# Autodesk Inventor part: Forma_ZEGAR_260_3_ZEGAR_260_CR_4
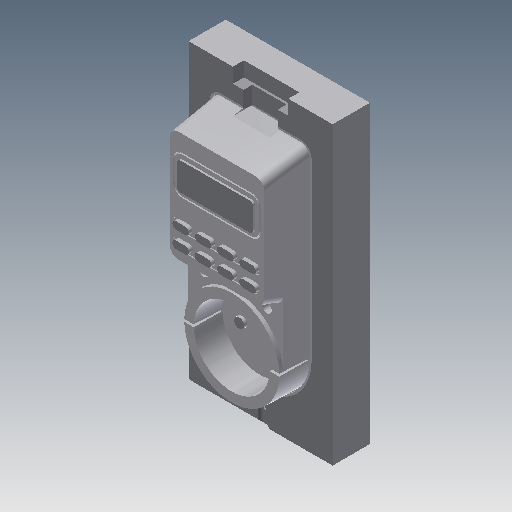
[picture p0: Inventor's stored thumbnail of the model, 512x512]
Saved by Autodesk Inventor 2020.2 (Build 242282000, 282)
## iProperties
Created: 2015-01
Part Number: Forma_ZEGAR_260_3_ZEGAR_260_CR_4
Material: Ogólny
Document SubType Name: Modeling
Designer: F.Stasiak
Density: 1 g/cm^3
Appearance: Domyślna
Catalog Web Link: www.expertbooks.pl
Manager: www.cadconsulting.pl
Company: Fabian Stasiak CAD Consulting
Author: F.Stasiak
Subject: Zbiór ćwiczeń. Autodesk Inventor 2020. Kurs Professional
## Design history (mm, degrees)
node "Forma_ZEGAR_260_3_ZEGAR_260_CR_Base"
feature "Rzeźbienie3"
feature "Bryła1::Forma_ZEGAR_260_3_ZEGAR_260_CR_Base"
tag "Bryła wyprowadzona1"
node "Bryła1"
feature "Forma_ZEGAR_260_3_ZEGAR_260_CR_Base_Bodies"
feature "Powierzchnia3"
body "Srf3"
